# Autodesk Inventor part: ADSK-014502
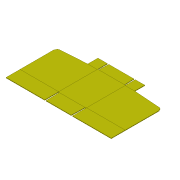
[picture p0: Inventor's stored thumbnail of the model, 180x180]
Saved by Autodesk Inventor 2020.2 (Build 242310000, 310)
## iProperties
Created: 2019-12
Part Number: ADSK-014502
Material: 1.0501 C35
Document SubType Name: Modeling
Designer: lutzd
Mass: 4498.25 g
Surface Area: 3974.72 cm^2
Volume: 573.756 cm^3
Density: 7.84 g/cm^3
Appearance: Gelb
VLDS_Profile: Default Part
VLDS_TimeStamp: 2016-07-29
VLDS_FailCnt: 0
VLDS_AcceptCnt: 0
Dimensions: 357,5x3x600 mm
Mass: 4,498 kg
DocNumber: ADSK-014502
Folder: 01 - Themengebiete\Simplification\01 - Packaging machine\Parts\
VDS_Category: 3D Komponenten
VDS_NumSchm: Autodesk
VLT_Material: 1.0501 C35
Title: box unfolded
Author: lutzd
Revision Number: -
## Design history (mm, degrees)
sketch "Skizze1"
  geometry: L1 (-79.5, -112.5)-(79.5, -112.5); L2 (79.5, -112.5)-(79.5, 112.5); L3 (79.5, 112.5)-(-79.5, 112.5); L4 (-79.5, 112.5)-(-79.5, -112.5); L5 (-79.5, -112.5)-(79.5, 112.5); L6 (79.5, -112.5)-(-79.5, 112.5); L7 (79.5, 110)-(133.5, 110); L8 (79.5, -110)-(300, -110); L9 (133.5, 110)-(285.372, 99.38); L10 (300, 98.357)-(300, 83.911); L11 (79.5, -112.5)-(79.5, -189.5); L12 (79.5, -189.5)-(300, -189.5); L13 (300, -189.5)-(300, -110); L14 (79.5, 112.5)-(79.5, 168); L15 (79.5, 168)-(133.5, 168); L16 (133.5, 168)-(133.5, 110); L17 (0, 112.5)-(0, -112.5); L18 (285.372, 99.38)-(300, 98.357); L19 (300, 83.911)-(300, -110); L20 (-73.5, -112.5)-(-71.5, -189.5); L21 (-71.5, -189.5)-(71.5, -189.5); L22 (71.5, -189.5)-(73.5, -112.5); L23 (-73.5, 112.5)-(-71.5, 168); L24 (-71.5, 168)-(71.5, 168); L25 (71.5, 168)-(73.5, 112.5); A1 r 12.5 centre (284.5, 86.911) between (297, 86.911) and (285.372, 99.38); A2 r 3 centre (300, 86.911) between (297, 86.911) and (300, 83.911); A3 r 12.5 centre (284.5, 86.911) between (297, 86.911) and (285.372, 99.38); 4 further points
  constraints: 50 end point, 7 midpoint, 7 point on line, 6 horizontal, 6 perpendicular, 6 point on circle, 4 tangent, 3 centre point, 2 collinear, 2 parallel, 2 vertical, 2 vertical alignment, 1 concentric
  dimensions: "d0" = 159 distance of L3.end L2.end; "d1" = 225 distance of L2.end L1.end; "d2" = 2.5 distance between parallel lines of L1 L8; "d3" = 2.5 distance between parallel lines of L3 L7 (= d2); "d4" = 54 distance of L7.start L7.end; "d5" = 220.5 distance of L8.start L8.end; "d6" = 4 deg angle of L7 L9; "d7" = 77 distance of L1.end L11.end; "d8" = 58 distance of L15.end L7.end; "d9" = 25 diameter of A1; "d10" = 15.5 distance from line of L10 A1.centre; "d11" = 3 radius of A2; "d12" = 6 distance of L1.start L20.start; "d13" = 6 distance from line of L11 L22.end (= d12); "d14" = 143 distance of L20.end L21.end; "d25" = 6 distance from line of L14 L25.end (= d12); "d26" = 6 distance from line of L4 L23.start (= d12); "d27" = 143 distance of L23.end L24.end (= d14)
extrude "Extrusion1" new body sketch "Skizze1" distance "d15" = 3 (= thickness); taper "d16" = 0 deg
extrude "Extrusion2" new body sketch "Skizze1" distance "d17" = 3 (= thickness); taper "d18" = 0 deg
extrude "Extrusion3" new body sketch "Skizze1" distance "d19" = 3 (= thickness); taper "d20" = 0 deg
extrude "Extrusion4" new body sketch "Skizze1" distance "d21" = 3 (= thickness); taper "d22" = 0 deg
extrude "Extrusion5" new body sketch "Skizze1" distance "d23" = 3 (= thickness); taper "d24" = 0 deg
mirror "Spiegeln1"
extrude "Extrusion6" new body sketch "Skizze1" distance "d28" = 3 (= thickness); taper "d29" = 0 deg
node "Volumenkörper1"
node "Volumenkörper2"
node "Volumenkörper3"
node "Volumenkörper4"
node "Volumenkörper5"
node "Volumenkörper6"
other parameters: "thickness" = 3 [user parameter; used in 6 equation terms]
